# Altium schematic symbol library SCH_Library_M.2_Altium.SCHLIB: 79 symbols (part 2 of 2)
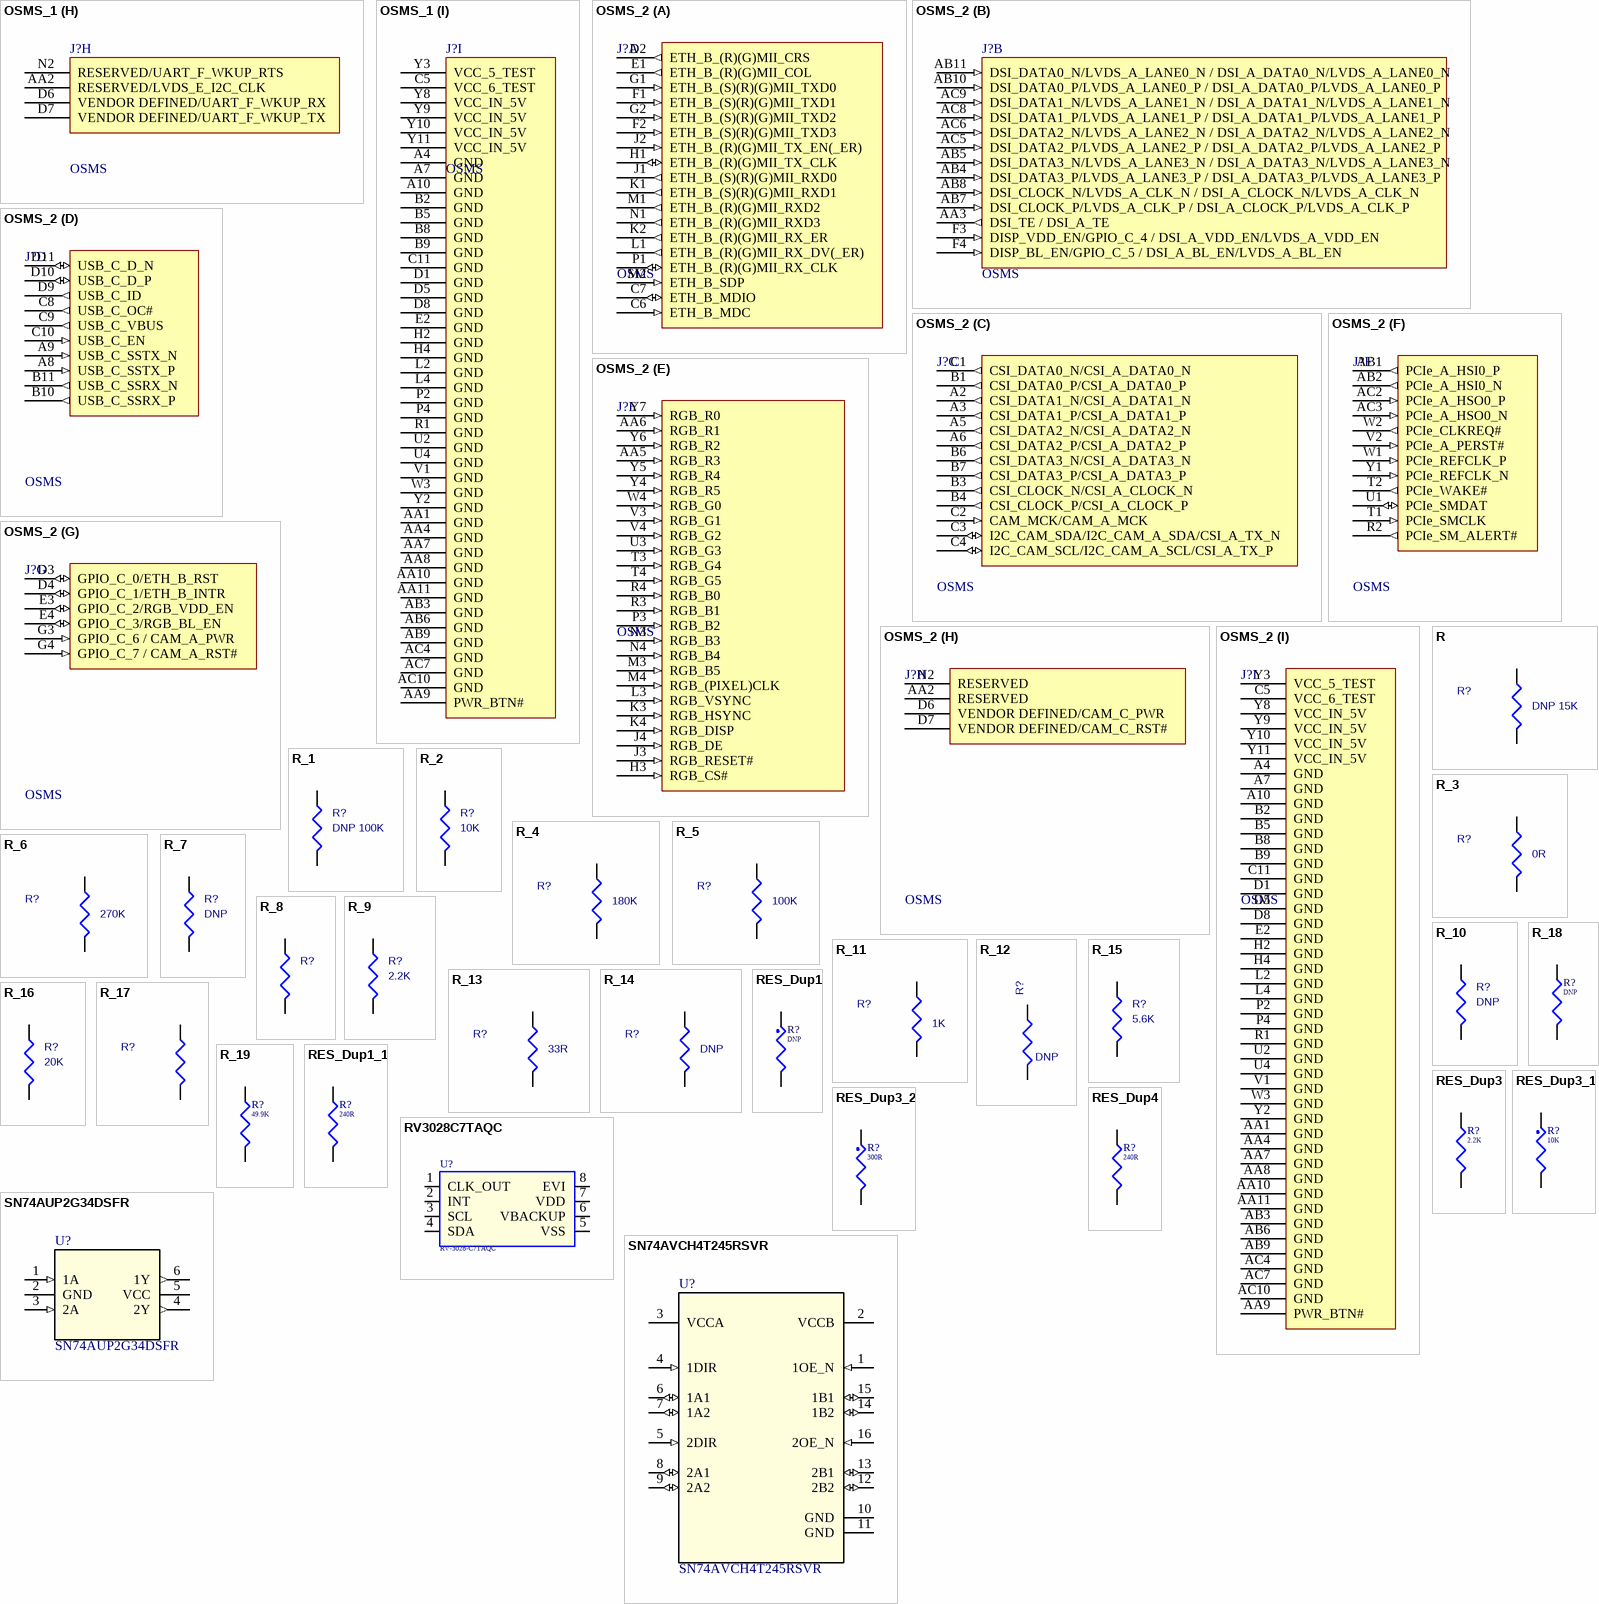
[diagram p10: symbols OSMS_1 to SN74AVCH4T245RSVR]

## RES_Dup3_2
designator R?, comment 300R
300R 1% 1/32W 01005; 01. ASET1 UI1: ------------; 01. Set1/BD#: BD3423; 02. Set1/MF1: Panasonic; 03. Set1/PN1: ERJ-U0XF3000Y; 09. Z Lay/FP: RES0402_1005
footprint RC0603_OV
footprint RES1608_0603
footprint RES0402_1005
pins: 1, 2

## RES_Dup4
designator R?, comment 240R
240R 1% 1/32W 01005; 01. ASET1 UI1: ------------; 01. Set1/BD#: BD3420; 02. Set1/MF1: Yageo; 03. Set1/PN1: RC0100FR-07240RL; 09. Z Lay/FP: RES0402_1005
footprint RES1005_0402
footprint RES0603_0201
footprint RES1608_0603
footprint RES01005_0402
footprint RES0402_1005
pins: 1, 2

## RV3028C7TAQC
designator U?, comment RV-3028-C7TAQC
RTC LOW POWER; 01. ASET1 UI1: ------------; 01. Set1/BD#: BD2265; 02. Set1/MF1: Micro Crystal; 09. Footprint/Package: IC 8pin 3.2mm x 1.5mm; 09. Z Lay/FP: RV-4162 C7_OSM
footprint RV-4162 C7
footprint RV-4162 C7_OSM
pins: 1 CLK_OUT, 2 INT, 3 SCL, 4 SDA, 5 VSS, 6 VBACKUP, 7 VDD, 8 EVI

## SN74AUP2G34DSFR
designator U?
IC BUFFER NON-INVERT 3.6V 6SON; 01. ASET1 UI1: ------------; 01. Set1/BD#: BD3718; 02. Set1/MF1: Texas Instruments
footprint DSF6
footprint SN74AUP2G34DSFR
pins: 1 1A (in), 2 GND (power), 3 2A (in), 4 2Y (out), 5 VCC (power), 6 1Y (out)

## SN74AVCH4T245RSVR
designator U?
IC TRANSLATION TXRX 3.6V 16UQFN; 01. ASET1 UI1: ------------; 01. Set1/BD#: BD3717; 02. Set1/MF1: Texas Instruments
footprint RSV0016A
footprint SN74AVCH4T245RSVR
pins: 1 1OE_N (in), 2 VCCB (power), 3 VCCA (power), 4 1DIR (in), 5 2DIR (in), 6 1A1 (io), 7 1A2 (io), 8 2A1 (io), 9 2A2 (io), 10 GND (power), 11 GND (power), 12 2B2 (io), 13 2B1 (io), 14 1B2 (io), 15 1B1 (io), 16 2OE_N (in)

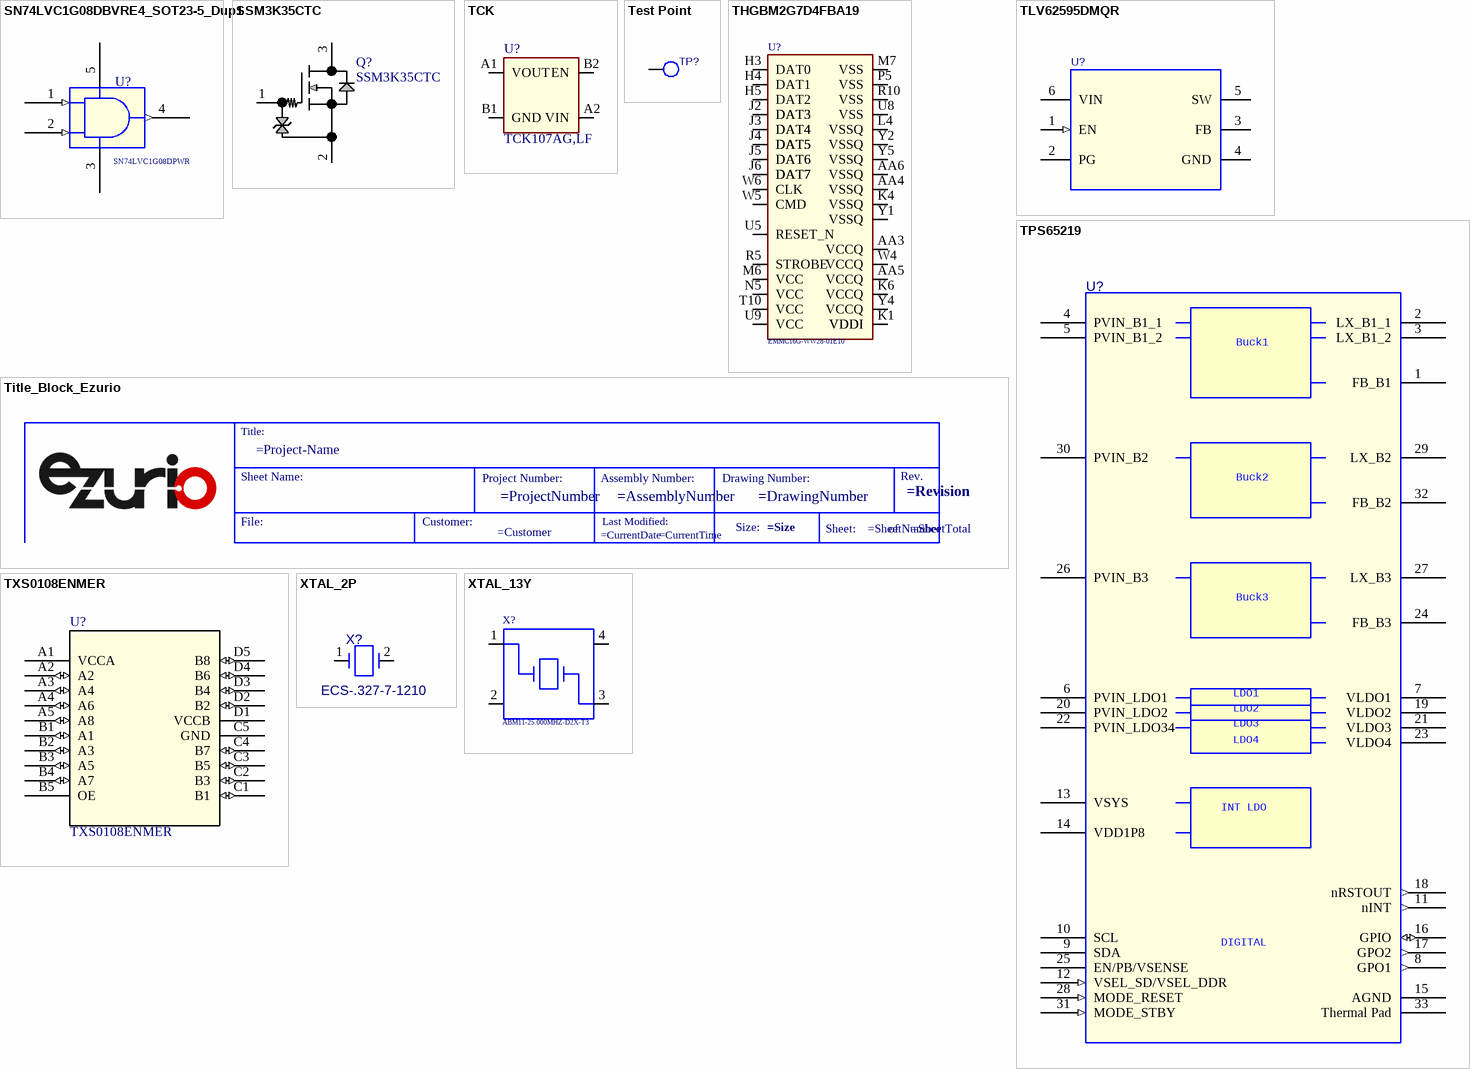
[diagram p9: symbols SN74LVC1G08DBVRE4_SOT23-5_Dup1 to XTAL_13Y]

## SN74LVC1G08DBVRE4_SOT23-5_Dup1
designator U?, comment SN74LVC1G08DPWR
IC GATE AND 1CH 2-INP 4X2SON; 01. ASET1 UI1: ------------; 01. Set1/BD#: BD3789; 02. Set1/MF1: Texas Instruments
footprint SOT23-5
footprint SN74LVC1G08DPWR
pins: 1 A (in), 2 B (in), 3 GND (power), 4 Y (out), 5 VCC (power)

## SSM3K35CTC
designator Q?
MOSFET N-CH 20V 250MA CST3C; 01. ASET1 UI1: ------------; 01. Set1/BD#: BD3417; 09. Z Lay/FP: SSM3K35CTC,L3F; 02. Set1/MF1: Toshiba Semiconductor
footprint SSM3K35CTC,L3F
pins: 1, 2, 3

## TCK
designator U?, comment TCK107AG,LF
IC PWR SWITCH P-CHAN 1:1 4WCSPD; 01. ASET1 UI1: ------------; 01. Set1/BD#: BD3329; 02. Set1/MF1: Toshiba
footprint TCK107AG,LF
pins: A1 VOUT, A2 VIN, B1 GND, B2 EN

## Test Point
designator TP?  (value not drawn)  (no BOM)
MISC, Test Point, Test Point, SMD, TP35S_SMD; 01. ASET1 UI1: ------------; 09. Z Lay/FP: TPAD_020_OSM
footprint tp1-8040
footprint TP35S_SMD
footprint tpad_020
footprint TPAD_020_OSM
pins: 1 TP

## THGBM2G7D4FBA19
designator U?, comment EMMC16G-WW28-01E10
16G EMMC Industrial; 01. ASET1 UI1: ------------; 01. Set1/BD#: BD3431; 02. Set1/MF1: Kingston; 09. Footprint/Package: BGA-153; 09. Z Lay/FP: THGBM2G7D4FBA19_2
footprint THGBM2G7D4FBA19_2
pins: AA3 VCCQ, AA4 VSSQ, AA5 VCCQ, AA6 VSSQ, H1 DAT3, H2 DAT4, H3 DAT0, H4 DAT1, H5 DAT2, H8 DAT7, J2 DAT3, J3 DAT4, J4 DAT5, J5 DAT6, J6 DAT7, J7 DAT7, K1 VDDI, K2 VDDI, K3 DAT5, K4 VSSQ, K5 DAT6, K6 VCCQ, L1 DAT5, L2 DAT5, L4 VSSQ, M6 VCC, M7 VSS, N5 VCC, P5 VSS, R5 STROBE, R10 VSS, T10 VCC, U5 RESET_N, U8 VSS, U9 VCC, W4 VCCQ, W5 CMD, W6 CLK, Y1 VSSQ, Y2 VSSQ, Y4 VCCQ, Y5 VSSQ

## Title_Block_Ezurio
designator ??  (value not drawn)  (graphical)

## TLV62595DMQR
designator U?  (value not drawn)
IC REG BUCK ADJ 4A 6VSON; 01. ASET1 UI1: ------------; 01. Set1/BD#: BD3327; 02. Set1/MF1: Texas Instruments
footprint vson6_0d5_1d5x1d5x1mm
footprint TLV62595DMQR
pins: 1 EN (in), 2 PG (oc), 3 FB, 4 GND (power), 5 SW, 6 VIN (power)

## TPS65219
designator U?, comment TPS6521920WRHBRQ1  (value not drawn)
Processor PMIC 32-VQFN (5x5); 01. ASET1 UI1: ------------; 01. Set1/BD#: BD3428; 02. Set1/MF1: Texas Instruments
footprint QFN32_5X5MM_TPS65219
footprint TPS6521920W
pins: 1 FB_B1, 2 LX_B1_1, 3 LX_B1_2, 4 PVIN_B1_1 (power), 5 PVIN_B1_2 (power), 6 PVIN_LDO1 (power), 7 VLDO1 (power), 8 GPO1 (out), 9 SDA, 10 SCL, 11 nINT (out), 12 VSEL_SD/VSEL_DDR (in), 13 VSYS (power), 14 VDD1P8, 15 AGND (power), 16 GPIO (io), 17 GPO2 (out), 18 nRSTOUT (out), 19 VLDO2 (power), 20 PVIN_LDO2 (power), 21 VLDO3 (power), 22 PVIN_LDO34 (power), 23 VLDO4 (power), 24 FB_B3, 25 EN/PB/VSENSE, 26 PVIN_B3 (power), 27 LX_B3, 28 MODE_RESET (in), 29 LX_B2, 30 PVIN_B2 (power), 31 MODE_STBY (in), 32 FB_B2, 33 Thermal Pad (power)

## TXS0108ENMER
designator U?
IC TRANSLATOR BIDIR 20NFBGA; 01. ASET1 UI1: ------------; 01. Set1/BD#: BD3427; 02. Set1/MF1: Texas Instruments
footprint TXS0108ENMER
pins: A1 VCCA (power), A2 (io), A3 A4 (io), A4 A6 (io), A5 A8 (io), B1 A1 (io), B2 A3 (io), B3 A5 (io), B4 A7 (io), B5 OE, C1 B1 (io), C2 B3 (io), C3 B5 (io), C4 B7 (io), C5 GND (power), D1 VCCB (power), D2 B2 (io), D3 B4 (io), D4 B6 (io), D5 B8 (io)

## XTAL_2P
designator X?, comment ECS-.327-7-1210
CRYSTAL 32.7680KHZ 7PF SMD; 01. ASET1 UI1: ------------; 01. Set1/BD#: BD3426; 02. Set1/MF1: ECS Inc.; 03. Set1/PN1: ECS-.327-7-1210-TR; 09. Z Lay/FP: XTAL_ECS-.327-7-1210-TR
footprint X2_SMD_3_2X1_5MM
footprint XTAL_ABS07
footprint XTAL_ECS-.327-7-1210-TR
pins: 1, 2

## XTAL_13Y
designator X?, comment ABM11-25.000MHZ-D2X-T3
CRYSTAL 25.0000MHZ 10PF SMD; 01. ASET1 UI1: ------------; 01. Set1/BD#: BD3424; 02. Set1/MF1: Abracon LLC; 09. Z Lay/FP: ECS-250-10-47Q-CES-TR
footprint XTAL_ABM11
footprint ECS-250-10-47Q-CES-TR
pins: 1, 2, 3, 4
